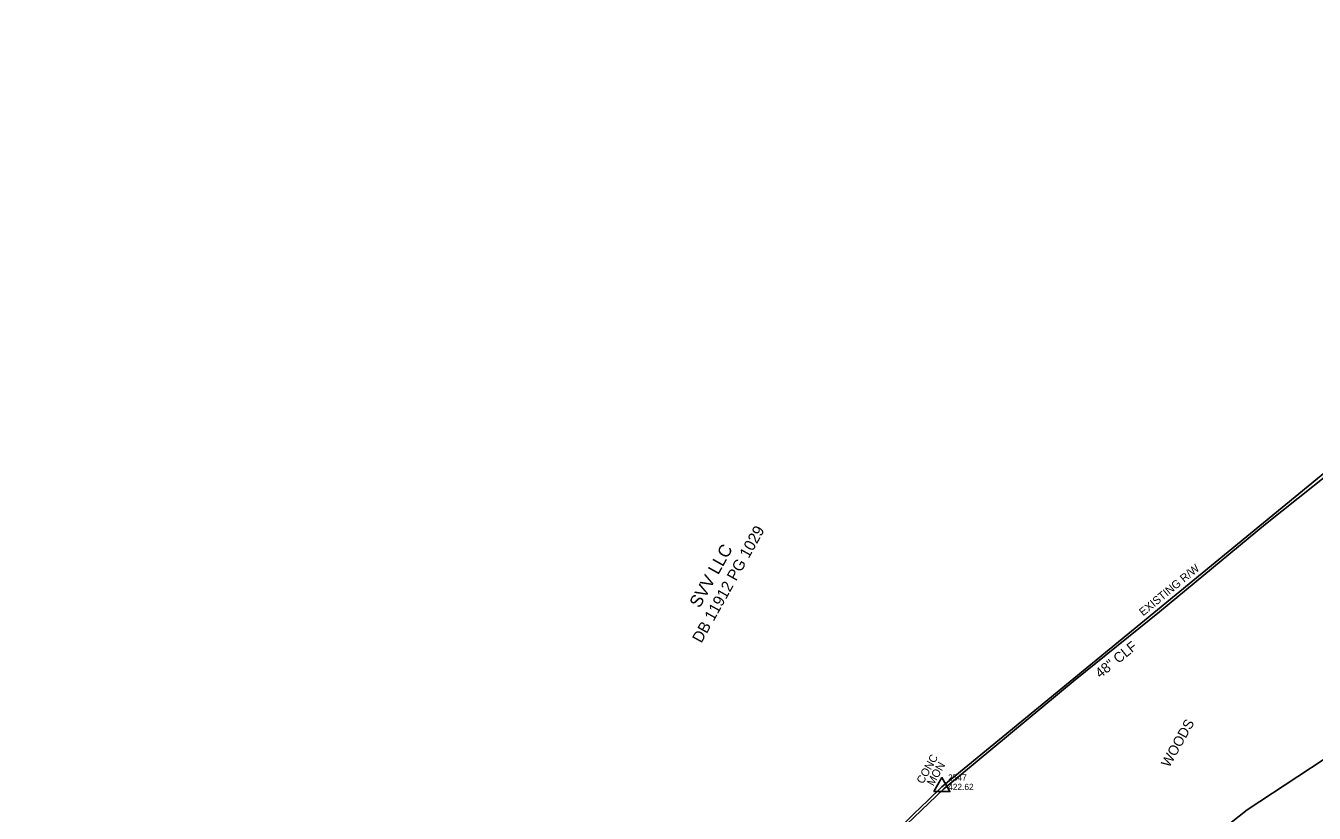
# Model space of a CAD drawing. Extents: x 2074109 to 2077820, y 741079 to 746031.
# Drawn here: x 2074923 to 2075439, y 744048 to 744363 of the extents above; entities that cross this region are included whole.
import ezdxf

# ---------------------------------------------------------------- set-up
doc = ezdxf.new("R2010")
doc.units = 0
for name, color, linetype in [('Exist Horizontal Alignment', 7, 'Continuous'), ('Exist Other Culture Fence Line', 7, 'Continuous'), ('Exist Other Culture Fence Line Text', 7, 'Continuous'), ('Exist Property Deed Book Text', 7, 'Continuous'), ('Exist Property Owner Text', 7, 'Continuous'), ('Exist Right of Way Line', 7, 'Continuous'), ('Exist Right of Way Line Text', 7, 'Continuous'), ('Exist Right of Way Monument CELL', 7, 'Continuous'), ('Exist Right of Way Monument Cogo Elevation', 7, 'Continuous'), ('Exist Right of Way Monument Cogo Number', 7, 'Continuous'), ('Exist Right of Way Monument Text', 7, 'Continuous'), ('Exist Vegetation Woods Line', 7, 'Continuous'), ('Exist Vegetation Woods Line Text', 7, 'Continuous')]:
    doc.layers.add(name, color=color, linetype=linetype)

msp = doc.modelspace()

# ---------------------------------------------------------------- linework, layer by layer
at = {"layer": 'Exist Horizontal Alignment'}
msp.add_arc((2078143.35, 740278.32), 4614.57, 123.47052, 126.11267, dxfattribs=at)
at = {"layer": 'Exist Other Culture Fence Line'}
msp.add_lwpolyline([(2075457.53, 744193.95), (2075418.99, 744163.3), (2075376.69, 744128.22), (2075342.98, 744101.03), (2075290.51, 744057.5), (2075257.43, 744025.88), (2075232.76, 743998.79), (2075209.84, 743969.34), (2075177.69, 743925.7), (2075155.96, 743894.11), (2075137.05, 743861.41), (2075119.77, 743830.25), (2075109.08, 743810.73), (2075088.01, 743773.33), (2075062.85, 743780.36), (2075019.43, 743795.39), (2074970.23, 743811.86), (2074919.89, 743828.65)], dxfattribs=at)
at = {"layer": 'Exist Right of Way Line'}
msp.add_line((2075289.65, 744058.22), (2075694.31, 744390.69), dxfattribs=at)
msp.add_arc((2075863.02, 743452.81), 833.83, 133.44231, 150.55169, dxfattribs=at)
at = {"layer": 'Exist Right of Way Monument CELL'}
msp.add_line((2075289.65, 744058.22), (2075289.65, 744058.22), dxfattribs=at)
msp.add_lwpolyline([(2075286.41, 744056.33), (2075289.65, 744061.97), (2075292.9, 744056.33)], close=True, dxfattribs=at)
at = {"layer": 'Exist Vegetation Woods Line'}
msp.add_lwpolyline([(2075556.35, 744153.49), (2075540.41, 744149.72), (2075518, 744127.44), (2075462.82, 744082.64), (2075411.72, 744049.01), (2075392.57, 744033.87)], dxfattribs=at)

# ---------------------------------------------------------------- texts
at = {"layer": 'Exist Other Culture Fence Line Text'}
msp.add_text('48" CLF', height=4, rotation=38.8865, dxfattribs=at).set_placement((2075352.97, 744101.53))
at = {"layer": 'Exist Property Deed Book Text'}
msp.add_text('DB 11912 PG 1029', height=4.5, rotation=60.8239, dxfattribs=at).set_placement((2075193.5, 744115.47))
at = {"layer": 'Exist Property Owner Text'}
msp.add_text('SVV LLC', height=5, rotation=60.8239, dxfattribs=at).set_placement((2075192.8, 744129.48))
at = {"layer": 'Exist Right of Way Line Text'}
msp.add_text('EXISTING R/W', height=3.2, rotation=39.4062, dxfattribs=at).set_placement((2075370.14, 744126.42))
at = {"layer": 'Exist Right of Way Monument Cogo Elevation'}
msp.add_text('422.62', height=2.5, dxfattribs=at).set_placement((2075292.15, 744056.97))
at = {"layer": 'Exist Right of Way Monument Cogo Number'}
msp.add_text('2547', height=2.5, dxfattribs=at).set_placement((2075292.15, 744060.72))
at = {"layer": 'Exist Right of Way Monument Text'}
for s, p in [('CONC', (2075282.11, 744059.16)), ('MON', (2075286.24, 744058.35))]:
    msp.add_text(s, height=3.2, rotation=60.742, dxfattribs=at).set_placement(p)
at = {"layer": 'Exist Vegetation Woods Line Text'}
msp.add_text('WOODS', height=4, rotation=60.742, dxfattribs=at).set_placement((2075380.57, 744065.73))

doc.saveas('drawing.dxf')
